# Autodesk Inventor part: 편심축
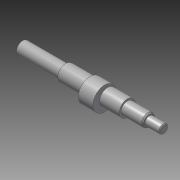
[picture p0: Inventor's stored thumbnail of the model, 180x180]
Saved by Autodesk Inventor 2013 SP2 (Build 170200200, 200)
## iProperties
Created: 2016-05
Part Number: 편심축
Document SubType Name: Modeling
Designer: mduedu
Density: 7.86 g/cm^3
Material: 강철, 연강
Author: mduedu
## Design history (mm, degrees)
sketch "스케치1"
  geometry: L1 (-37, 11)-(-37, 8.5); L2 (47, 11)-(47, 8.5); L3 (-97, 0)-(97, 0); L4 (-37, 11)-(47, 11); L5 (47, 11)-(47, 8.5); L6 (-37, 11)-(-37, 8.5); L7 (-37, 8.5)-(-97, 8.5); L8 (-97, 8.5)-(-97, 0); L9 (47, 8.5)-(77, 8.5); L10 (97, 6)-(97, 0); L11 (77, 8.5)-(77, 6); L12 (77, 6)-(97, 6); 1 further point
  constraints: 24 end point, 9 perpendicular, 2 midpoint, 1 collinear, 1 horizontal
  dimensions: "d0" = 22 diameter of L4 L3; "d1" = 17 diameter of L7 L3; "d2" = 60 distance between parallel lines of L8 L1; "d3" = 50 distance between parallel lines of L10 L2; "d4" = 12 diameter of L12 L3; "d5" = 20 distance between parallel lines of L10 L11; "d29" = 84 distance of L1.start L2.start
revolve "회전1" stored, may be unused: angle "d6" = 90 deg
node "작업 평면7"
node "작업 평면9"
sketch "스케치2"
  geometry: C1 r 11 at (0, 0); C2 r 16 at (0, -4); C3 r 11 at (0, 0); 2 further points
  constraints: 3 centre point, 2 coincident, 1 concentric, 1 vertical alignment
  dimensions: "d9" = 4 distance of point (0, 0) C2.centre; "d10" = 32 diameter of C2
extrude "돌출1" join sketch "스케치2" stored distance "d11" = 20; taper "d12" = 0 deg
chamfer "모따기2" distance "d32" = 1; stored, may be unused: second distance "d33" = 2, angle "d34" = 45 deg
node "작업 평면4"
sketch "스케치4"
  geometry: L1 (-5, 2)-(5, 2); L2 (5, -2)-(-5, -2); L3 (-10, -5)-(-10, 5) reference; A1 r 2 centre (5, 0) between (5, -2) and (5, 2); A2 r 2 centre (-5, 0) between (-5, 2) and (-5, -2); 2 further points
  constraints: 4 end point, 4 point on circle, 4 tangent, 2 centre point, 2 horizontal alignment, 1 midpoint, 1 parallel
  dimensions: "d20" = 4 distance between parallel lines of L2 L1; "d21" = 14 dimension on A1 A2; "d35" = 3 distance edge to line of A2 L3
extrude "돌출3" cut sketch "스케치4" distance "d23" = 2.5; taper "d24" = 0 deg
node "작업 평면5"
sketch "스케치5"
  geometry: L1 (30, 2.5)-(12.5, 2.5); L2 (12.5, -2.5)-(30, -2.5); L3 (30, 7.5)-(30, -7.5) reference; A1 r 2.5 centre (12.5, 0) between (12.5, 2.5) and (12.5, -2.5); 2 further points
  constraints: 4 end point, 2 point on circle, 2 point on line, 2 tangent, 1 centre point, 1 horizontal, 1 horizontal alignment, 1 midpoint
  dimensions: "d25" = 5 distance between parallel lines of L2 L1; "d36" = 20 dimension on A1 L3
extrude "돌출4" cut sketch "스케치5" distance "d27" = 3; taper "d28" = 0 deg
chamfer "모따기3" distance "d37" = 1.82; stored, may be unused: second distance "d38" = 2, angle "d39" = 30 deg
fillet "모깎기1" dims "d40" = 2, "d41" = 0.5
node "솔리드1"
other parameters: "d31" = -37
